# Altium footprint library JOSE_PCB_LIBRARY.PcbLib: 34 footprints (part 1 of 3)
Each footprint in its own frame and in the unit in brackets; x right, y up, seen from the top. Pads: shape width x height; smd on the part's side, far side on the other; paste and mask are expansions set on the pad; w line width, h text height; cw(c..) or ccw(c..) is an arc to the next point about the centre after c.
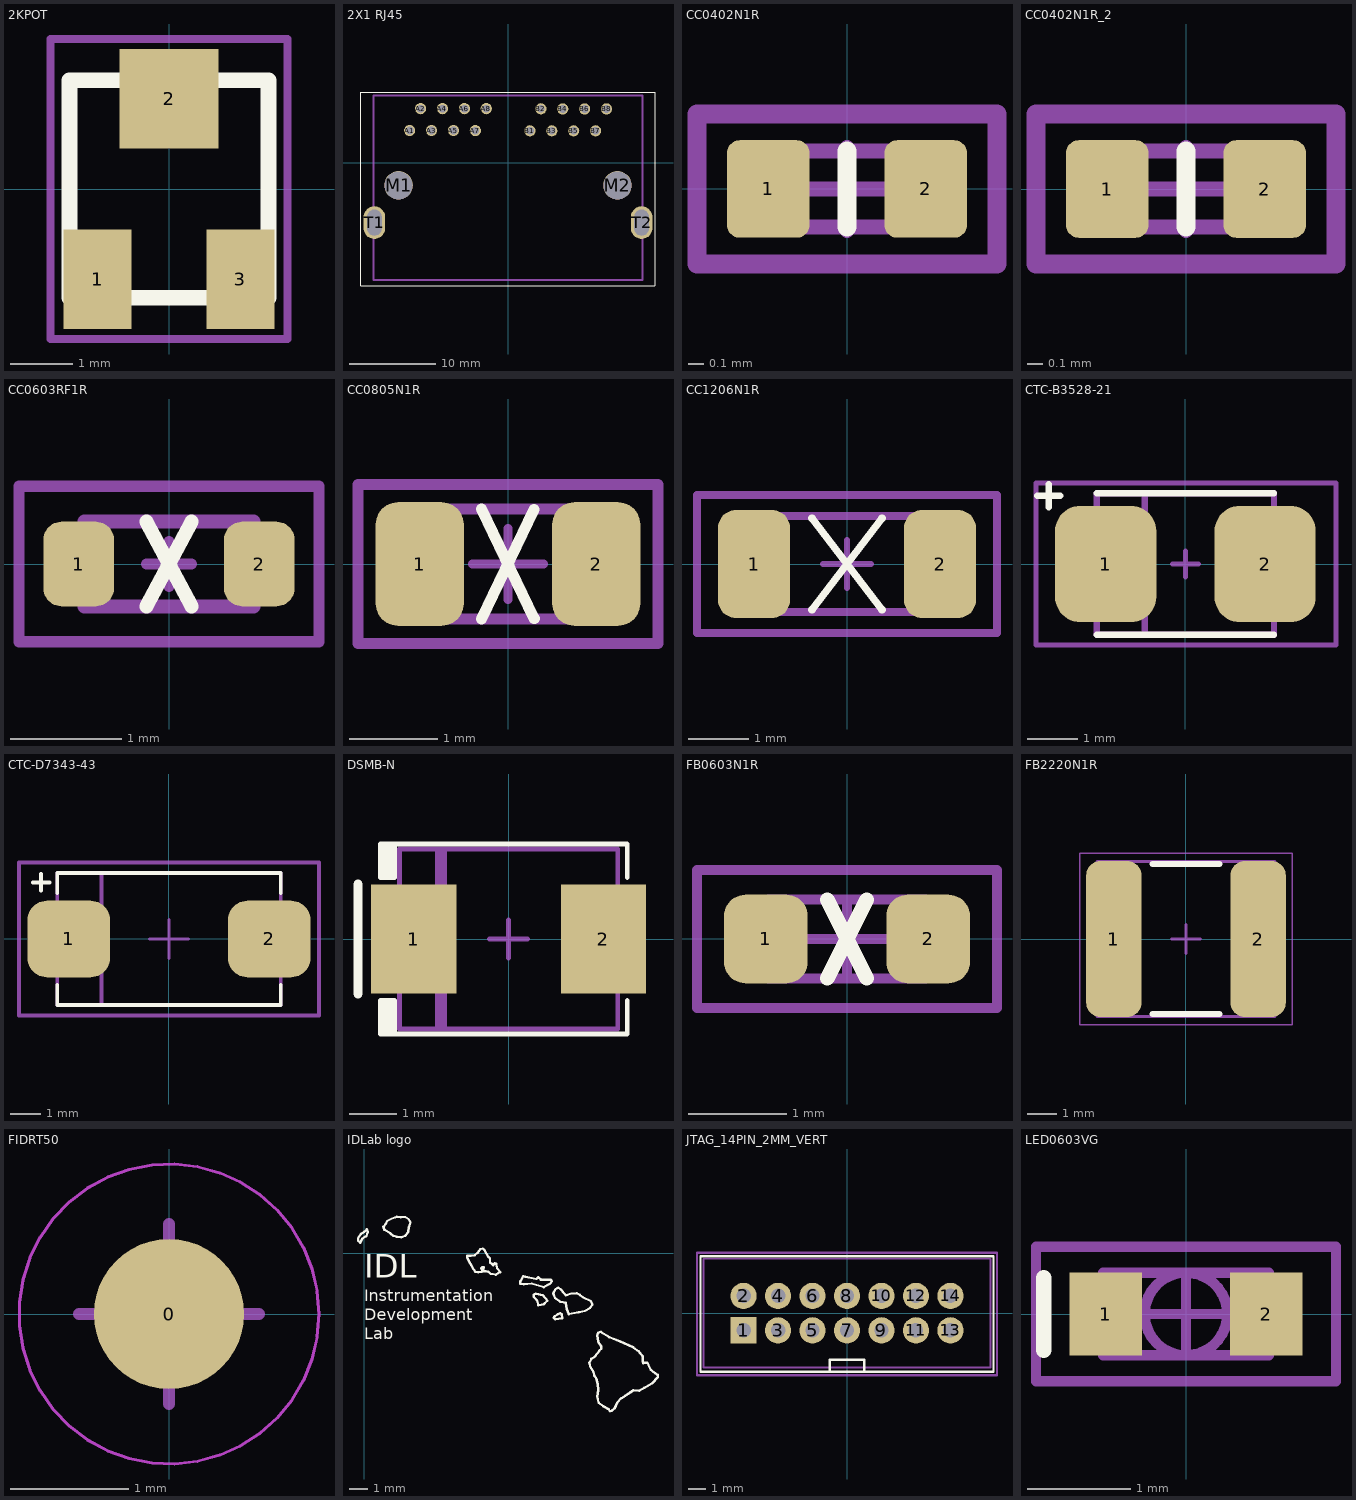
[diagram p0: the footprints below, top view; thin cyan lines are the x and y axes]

## 2KPOT [mm] "TRIMMER 2K OHM 0.125W SMD"
height 2.77
pads (3):
  rect 1.1x1.6 smd: 1(-1.15,-1.45) 3(1.15,-1.45)
  rect 1.6x1.6 smd: 2(0,1.45)
Top Overlay:
  lines w0.254: -1.6,-1.75 1.6,-1.75 1.6,1.75 -1.6,1.75 -1.6,-1.75
Mechanical 15:
  lines w0.127: -1.905,-2.413 -1.905,2.032 -1.905,2.413 -1.524,2.413 1.905,2.413 1.905,-2.413 -1.905,-2.413
3D body: height 2.77, standoff 0, extent -1.6,-1.75 1.6,1.75

## 2X1 RJ45 [mm] "DOUBLE_RIGHT ANGLE_RJ-45"
height 25.14
pads (20):
  round 1.3 hole 0.9: A1(-11.41,3.745) A2(-10.14,6.285) A3(-8.87,3.745) A4(-7.6,6.285) A5(-6.33,3.745) A6(-5.06,6.285) A7(-3.79,3.735) A8(-2.52,6.285) B1(2.54,3.715) B2(3.81,6.265) B3(5.08,3.715) B4(6.35,6.255) B5(7.62,3.715) B6(8.89,6.255) B7(10.16,3.715) B8(11.43,6.255)
  round 3.302 hole 3.25 unplated: M1(-12.7,-2.605) M2(12.7,-2.605)
  oval 2.5x3.8 hole 1.7 slot 3 at 90 deg: T1(-15.5,-6.935) T2(15.5,-6.935)
Top Overlay:
  lines w0.127: -17.1,-14.285 -17.1,8.215 17,8.215 17,-14.285 -17.1,-14.285
Mechanical 13:
  lines w0.254: -15.586,-13.585 15.6,-13.585 15.6,7.815 -15.586,7.815 -15.586,-13.585
3D body "615016137621 (rev1).stp": height 13.65, standoff -3.95, extent -15.6,-13.52 15.53,7.75

## CC0402N1R [mm] "Chip capacitor 0402 ROUND pad"
height 0.5
pads (2):
  rrect30% 0.55x0.65 smd mask+0.025: 1(-0.525,0) 2(0.525,0)
Top Overlay:
  lines w0.127: 0,-0.254 0,0.254
Mechanical 13:
  lines w0.1: -0.508,-0.254 0.508,-0.254 0.508,0.254 -0.508,0.254 -0.508,-0.254
Mechanical 15:
  lines w0.102: -0.3,0 0.3,0 ; 0,-0.275 0,0.275
  lines w0.127: -1,-0.5 -1,0.5 1,0.5 1,-0.5 -1,-0.5
3D body: height 0.5, standoff 0, extent -0.3,-0.254 0.3,0.254
3D body: height 0.5, standoff 0, extent 0.3,-0.254 0.508,0.254
3D body: height 0.5, standoff 0, extent -0.508,-0.254 -0.3,0.254

## CC0402N1R_2 [mm]
pads (2):
  rrect30% 0.55x0.65 smd mask+0.025: 1(-0.525,0) 2(0.525,0)
Top Overlay:
  lines w0.127: 0,-0.254 0,0.254
Mechanical 13:
  lines w0.1: -0.508,-0.254 0.508,-0.254 0.508,0.254 -0.508,0.254 -0.508,-0.254
Mechanical 15:
  lines w0.102: -0.3,0 0.3,0 ; 0,-0.275 0,0.275
  lines w0.127: -1,-0.5 -1,0.5 1,0.5 1,-0.5 -1,-0.5
3D body: height 0.5, standoff 0, extent -0.3,-0.254 0.3,0.254
3D body: height 0.5, standoff 0, extent 0.3,-0.254 0.508,0.254
3D body: height 0.5, standoff 0, extent -0.508,-0.254 -0.3,0.254

## CC0603RF1R [mil] "Chip capacitor 0603 RF pad ROUNDED PAD"
height 17.72
pads (2):
  rrect50% 25x30 smd: 1(-32,0) 2(32,0)
Top Overlay:
  lines w5: -8,-15 8,15 ; -8,15 8,-15
Mechanical 13:
  lines w5: -30,-15 30,-15 30,15 -30,15 -30,-15
Mechanical 15:
  lines w3.94: -7.87,0 7.87,0 ; 0,-7.87 0,7.87
  lines w4: -53.15,-27.56 -53.15,27.56 53.15,27.56 53.15,-27.56 -53.15,-27.56
3D body: height 27.56, standoff 0, extent -20,-15 20,15
3D body: height 27.56, standoff 0, extent 20,-15 30,15
3D body: height 27.56, standoff 0, extent -30,-15 -20,15

## CC0805N1R [mm] "Chip capacitor  0805 ROUND PAD"
height 1.35
pads (2):
  rrect50% 1x1.4 smd: 1(-1,0) 2(1,0)
Top Overlay:
  lines w0.127: -0.3,-0.625 0.296,0.616 ; -0.3,0.625 0.296,-0.618
Mechanical 13:
  lines w0.127: -1,-0.625 1,-0.625 1,0.625 -1,0.625 -1,-0.625
Mechanical 15:
  lines w0.102: -0.4,0 0.4,0 ; 0,-0.4 0,0.4
  lines w0.127: -1.7,-0.9 1.7,-0.9 1.7,0.9 -1.7,0.9 -1.7,-0.9
3D body: height 1, standoff 0, extent -1,-0.625 -0.6,0.625
3D body: height 1, standoff 0, extent 0.6,-0.625 1,0.625
3D body: height 1, standoff 0, extent -0.6,-0.625 0.6,0.625

## CC1206N1R [mm] "Chip capacitor 1206 ROUNDED PAD"
height 1.3
pads (2):
  rrect50% 1.2x1.8 smd: 1(-1.55,0) 2(1.55,0)
Top Overlay:
  lines w0.127: -0.584,-0.762 0.584,0.762 ; -0.584,0.762 0.584,-0.762
Mechanical 13:
  lines w0.127: -1.6,-0.8 -1.6,0.8 1.6,0.8 1.6,-0.8 -1.6,-0.8
Mechanical 15:
  lines w0.102: -0.4,0 0.4,0 ; 0,-0.4 0,0.4
  lines w0.127: -2.5,-1.15 2.5,-1.15 2.5,1.15 -2.5,1.15 -2.5,-1.15
3D body: height 1.35, standoff 0, extent -1.1,-0.8 1.1,0.8
3D body: height 1.35, standoff 0, extent -1.6,-0.8 -1.1,0.8
3D body: height 1.35, standoff 0, extent 1.1,-0.8 1.6,0.8

## CTC-B3528-21 [mm] "Capacitor Tantal Chip B - 3528, H=1.9mm"
height 1.9
pads (2):
  rrect50% 2x2.3 smd: 1(-1.575,0) 2(1.575,0)
Top Overlay:
  lines w0.127: -2.925,1.35 -2.475,1.35 ; -2.7,1.125 -2.7,1.575 ; -1.75,-1.4 1.75,-1.4 ; -1.75,1.4 1.75,1.4
Mechanical 13:
  lines w0.127: -1.525,0 -1.025,0 ; -1.275,-0.25 -1.275,0.25 ; -0.8,-1.4 -0.8,1.4 ; -1.75,-1.4 -1.75,1.4 1.75,1.4 1.75,-1.4 -1.75,-1.4
Mechanical 15:
  lines w0.1: -0.254,0 0.254,0 ; 0,-0.254 0,0.254
  lines w0.102: -2.95,-1.6 -2.95,1.6 2.975,1.6 2.975,-1.6 -2.95,-1.6
3D body: height 1.91, standoff 1.9, extent -1.75,-1.4 -0.8,1.4
3D body: height 1.9, standoff 0, extent -1.75,-1.4 1.75,1.4
3D body: height 1, standoff 0, extent 1.75,-1 1.925,1
3D body: height 1, standoff 0, extent -1.925,-1 -1.75,1

## CTC-D7343-43 [mm] "Capacitor Tantal Chip D - 7343, H=4.3mm"
height 4.3
pads (2):
  rrect50% 2.7x2.5 smd: 1(-3.275,0) 2(3.275,0)
Top Overlay:
  lines w0.127: -4.45,1.85 -3.9,1.85 ; -4.175,1.575 -4.175,2.125 ; -3.65,-1.5 -3.65,-2.15 3.65,-2.15 3.65,-1.5 ; -3.65,1.5 -3.65,2.15 3.65,2.15 3.65,1.5
Mechanical 13:
  lines w0.127: -3.25,0 -2.65,0 ; -2.95,-0.3 -2.95,0.3 ; -2.2,-2.15 -2.2,2.15 ; -3.65,-2.15 -3.65,2.15 3.65,2.15 3.65,-2.15 -3.65,-2.15
Mechanical 15:
  lines w0.102: -0.635,0 0.635,0 ; 0,-0.635 0,0.635
  lines w0.127: -4.9,-2.5 4.9,-2.5 4.9,2.5 -4.9,2.5 -4.9,-2.5
3D body: height 2.3, standoff 0, extent 3.65,-1.1 4,1.1
3D body: height 2.3, standoff 0, extent -4,-1.1 -3.65,1.1
3D body: height 4.3, standoff 0, extent -3.65,-2.15 3.65,2.15
3D body: height 4.31, standoff 4.3, extent -3.65,-2.15 -2.2,2.15

## DSMB-N [mm] "DIODE SMB normal"
height 2.4
pads (2):
  rect 1.8x2.3 smd: 1(-2,0) 2(2,0)
Top Overlay:
  lines w0.102: -2.5,-1.3 -2.5,-2 ; -2.5,1.3 -2.5,2 ; -2.4,-2 -2.4,-1.3 -2.6,-1.3 ; -2.4,2 -2.4,1.3 -2.6,1.3 ; 2.5,-1.3 2.5,-2 -2.5,-2 ; 2.5,1.3 2.5,2 -2.5,2 ; -2.6,-2 -2.6,-1.3 ; -2.6,-2 -2.5,-2 ; -2.6,-2 -2.7,-2 -2.7,-1.3 -2.6,-1.3 ; -2.6,1.3 -2.6,2 ; -2.6,1.3 -2.7,1.3 -2.7,2 -2.6,2 ; -2.6,2 -2.5,2
  lines w0.2: -3.175,-1.15 -3.175,1.15
Mechanical 13:
  lines w0.102: -2.3,-1 -2.6,-1 -2.6,1 -2.3,1 ; -1.5,-1.9 -1.5,1.9 ; -1.425,-1.9 -1.425,1.9 ; -1.35,-1.9 -1.35,1.9 ; 2.3,-1 2.6,-1 2.6,1 2.3,1 ; -2.3,-1.9 2.3,-1.9 2.3,1.9 -2.3,1.9 -2.3,-1.9
Mechanical 15:
  lines w0.102: -0.4,0 0.4,0 ; 0,-0.4 0,0.4
3D body: height 2.4, standoff 0, extent -2.3,-1.9 2.3,1.9
3D body: height 1.4, standoff 0, extent -2.6,-1 -2.3,1
3D body: height 1.4, standoff 0, extent 2.3,-1 2.6,1
3D body: height 2.41, standoff 2.4, extent -1.725,-1.9 -1.3,1.9

## FB0603N1R [mm] "Chip Ferrite Bead, 2-Leads, Body 1,6x0,8mm, IPC Medium Density"
height 0.8
pads (2):
  rrect50% 0.85x0.9 smd: 1(-0.825,0) 2(0.825,0)
Top Overlay:
  lines w0.15: -0.2,-0.4 0.2,0.4 ; -0.2,0.4 0.2,-0.4
Mechanical 13:
  lines w0.1: -0.8,-0.4 0.8,-0.4 0.8,0.4 -0.8,0.4 -0.8,-0.4
Mechanical 15:
  lines w0.1: -0.4,0 0.4,0 ; 0,-0.4 0,0.4 ; -1.525,-0.7 1.525,-0.7 1.525,0.7 -1.525,0.7 -1.525,-0.7
3D body: height 0.8, standoff 0, extent -0.4,-0.4 0.4,0.4
3D body: height 0.8, standoff 0, extent -0.8,-0.4 -0.4,0.4
3D body: height 0.8, standoff 0, extent 0.4,-0.4 0.8,0.4

## FB2220N1R [mm] "Chip Ferrite, 2-Leads, Body 5,59x5,08mm, IPC Medium Density"
height 2.05
pads (2):
  rrect50% 1.9x5.35 smd: 1(-2.475,0) 2(2.475,0)
Top Overlay:
  lines w0.2: -1.15,-2.575 1.15,-2.575 ; -1.15,2.575 1.15,2.575
Mechanical 13:
  lines w0.1: -3.05,-2.665 3.05,-2.665 3.05,2.665 -3.05,2.665 -3.05,-2.665
Mechanical 15:
  lines w0.05: -3.65,-2.95 3.65,-2.95 3.65,2.95 -3.65,2.95 -3.65,-2.95
  lines w0.1: -0.5,0 0.5,0 ; 0,-0.5 0,0.5
3D body: height 2.05, standoff 0, extent 2.29,-2.665 3.05,2.665
3D body: height 2.05, standoff 0, extent -3.05,-2.665 -2.29,2.665
3D body: height 2.05, standoff 0, extent -2.29,-2.665 2.29,2.665

## FIDRT50 [mm] "Fiducial TOP round 50mil"
height 0.5
pads (1):
  round 1.27 smd paste-2.54 mask+0.635: 0(0,0)
Top Layer keep-out:
  circle w0.025: c0,0 r1.27
Mechanical 13:
  circle w0.025: c0,0 r1.27
Mechanical 15:
  lines w0.102: -0.762,0 0.762,0 ; 0,-0.762 0,0.762

## IDLab logo [mm]
height 0.5
Top Overlay:
  drawing of 160 lines, arcs and shapes, not listed
  text "IDL" at -0.015,-1.288 h1.27
  text "Instrumentation" at -0.015,-2.558 h0.64
  text "Development" at -0.015,-3.574 h0.64
  text "Lab" at -0.015,-4.59 h0.64

## JTAG_14PIN_2MM_VERT [mil]
height 173.23
pads (14):
  rect 60x60 hole 33: 1(-236.22,-39.37)
  round 60 hole 33: 2(-236.22,39.37) 3(-157.48,-39.37) 4(-157.48,39.37) 5(-78.74,-39.37) 6(-78.74,39.37) 7(0,-39.37) 8(0,39.37) 9(78.74,-39.37) 10(78.74,39.37) 11(157.48,-39.37) 12(157.48,39.37) 13(236.22,-39.37) 14(236.22,39.37)
Top Overlay:
  lines w5: -39.37,-133.86 -39.37,-106.3 39.37,-106.3 39.37,-133.86 ; -334.65,-133.86 334.65,-133.86 334.65,129.92 -334.65,129.92 -334.65,-133.86
Mechanical 13:
  lines w3.94: -327.75,-124.01 -327.75,124.02 327.76,124.02 327.76,-124.01 -327.75,-124.01
Mechanical 15:
  lines w3.94: 342.52,-141.73 342.52,137.8
  lines w5: 342.52,-141.73 -342.52,-141.73 -342.52,137.8 342.52,137.8
3D body "878311420.stp": height 253.94, standoff -96.46, extent -327.75,-124.01 327.76,124.02

## LED0603VG [mm] "LED chip 0603 1.6x0.8x0.6mm vertical Green"
height 0.6
pads (2):
  rect 0.7x0.8 smd: 1(-0.775,0) 2(0.775,0)
Top Overlay:
  lines w0.15: -1.375,-0.35 -1.375,0.35
Mechanical 13:
  circle w0.102: c0,0 r0.4
  rectangle: -0.8,-0.4 -0.5,0.4
  lines w0.1: -0.8,-0.4 0.8,-0.4 0.8,0.4 -0.8,0.4 -0.8,-0.4
Mechanical 15:
  lines w0.1: -0.4,0 0.4,0 ; 0,-0.4 0,0.4 ; -1.45,-0.65 1.45,-0.65 1.45,0.65 -1.45,0.65 -1.45,-0.65
3D body: height 0.6, standoff 0.3, extent -0.8,-0.4 0.8,0.4
3D body: height 0.3, standoff 0, extent -0.8,-0.4 0.8,0.4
